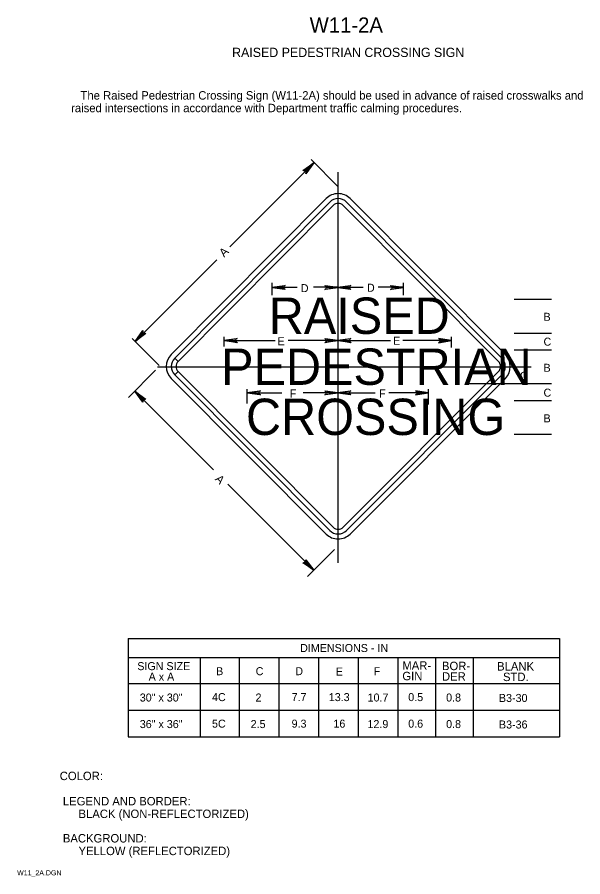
# Model space of a CAD drawing. Extents: x 0.013 to 0.18, y 0.004 to 0.259.
import ezdxf

# ---------------------------------------------------------------- set-up
doc = ezdxf.new("R2010")
doc.units = 0
for name, color, linetype in [('1', 7, 'Continuous'), ('2', 7, 'Continuous'), ('3', 7, 'Continuous')]:
    doc.layers.add(name, color=color, linetype=linetype)

msp = doc.modelspace()

# ---------------------------------------------------------------- linework, layer by layer
at = {"layer": '3'}
for p, q in [((0.07565765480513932, 0.1907872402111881), (0.10068094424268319, 0.21581052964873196)), ((0.10784039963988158, 0.20865107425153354), (0.09979705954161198, 0.21669441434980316)), ((0.10775, 0.213), (0.10775, 0.097125)), ((0.10426909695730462, 0.20512639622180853), (0.058315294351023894, 0.1588474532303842)), ((0.10532391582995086, 0.20407898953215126), (0.059370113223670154, 0.15780004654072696)), ((0.1563694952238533, 0.15780297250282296), (0.11030730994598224, 0.20408192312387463)), ((0.15742308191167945, 0.1588516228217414), (0.11136089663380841, 0.20513057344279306)), ((0.060368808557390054, 0.15680836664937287), (0.10632261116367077, 0.20308730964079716)), ((0.1093097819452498, 0.20308906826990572), (0.15537196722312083, 0.15681011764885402)), ((0.07180950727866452, 0.18693909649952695), (0.04762678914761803, 0.16275637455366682)), ((0.08825, 0.1765), (0.08825, 0.180125)), ((0.08831289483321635, 0.1788202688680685), (0.09562780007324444, 0.1788202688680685)), ((0.10781289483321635, 0.1788202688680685), (0.10056770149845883, 0.1788202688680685)), ((0.10781289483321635, 0.1788202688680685), (0.1152776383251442, 0.1788202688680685)), ((0.12731289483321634, 0.1788202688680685), (0.11966866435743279, 0.1788202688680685)), ((0.12725, 0.1765), (0.12725, 0.180125)), ((0.16, 0.17525000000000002), (0.171125, 0.17525000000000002)), ((0.05478624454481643, 0.1555969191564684), (0.04674290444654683, 0.163640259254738)), ((0.074, 0.16125), (0.074, 0.164125)), ((0.14150000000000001, 0.161), (0.14150000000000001, 0.164125)), ((0.16, 0.16525), (0.171125, 0.16525)), ((0.07406289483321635, 0.16303984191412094), (0.0891382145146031, 0.16303984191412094)), ((0.10781289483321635, 0.16303984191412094), (0.0929803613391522, 0.16303984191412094)), ((0.10781289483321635, 0.16303984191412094), (0.1233882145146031, 0.16303984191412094)), ((0.14156289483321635, 0.16303984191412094), (0.12701081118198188, 0.16303984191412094)), ((0.16, 0.16025), (0.171125, 0.16025)), ((0.059370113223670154, 0.15780004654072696), (0.060368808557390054, 0.15680836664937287)), ((0.060368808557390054, 0.15680836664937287), (0.059370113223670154, 0.15780004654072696)), ((0.05365338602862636, 0.15418554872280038), (0.045610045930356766, 0.14614221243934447)), ((0.05425, 0.15525), (0.16, 0.15525)), ((0.06037055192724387, 0.1538386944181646), (0.05937302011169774, 0.15284583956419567)), ((0.05937302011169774, 0.15284583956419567), (0.06037055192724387, 0.1538386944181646)), ((0.10632448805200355, 0.107667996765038), (0.060370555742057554, 0.1538386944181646)), ((0.1553702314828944, 0.15383693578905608), (0.10930817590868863, 0.10766624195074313)), ((0.16, 0.15525), (0.165125, 0.15525)), ((0.05831942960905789, 0.15179719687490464), (0.10427336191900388, 0.10562649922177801)), ((0.05937302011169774, 0.15284583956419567), (0.10532695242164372, 0.10667514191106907)), ((0.11030454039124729, 0.10667221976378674), (0.15636659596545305, 0.1528429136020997)), ((0.11135689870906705, 0.10562233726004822), (0.1574189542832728, 0.15179303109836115)), ((0.07086336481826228, 0.12464758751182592), (0.047489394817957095, 0.14802155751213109)), ((0.080875, 0.144375), (0.080875, 0.148625)), ((0.134625, 0.14400000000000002), (0.134625, 0.148625)), ((0.146, 0.15025), (0.171125, 0.15025)), ((0.08093789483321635, 0.14749420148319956), (0.091135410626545, 0.14749420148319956)), ((0.10781289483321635, 0.14749420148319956), (0.09748303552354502, 0.14749420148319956)), ((0.10781289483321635, 0.14753984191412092), (0.1187776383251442, 0.14753984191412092)), ((0.13468789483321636, 0.14753984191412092), (0.12283933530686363, 0.14753984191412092)), ((0.16, 0.14525), (0.171125, 0.14525)), ((0.16, 0.13525), (0.171125, 0.13525)), ((0.0751435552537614, 0.1203673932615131), (0.10062275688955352, 0.09488819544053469)), ((0.10678673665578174, 0.10105217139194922), (0.09874339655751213, 0.09300883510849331)), ((0.0455, 0.074625), (0.17350000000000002, 0.074625)), ((0.0455, 0.074625), (0.0455, 0.0455)), ((0.17350000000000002, 0.074625), (0.17350000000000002, 0.0455)), ((0.17350000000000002, 0.068875), (0.0455, 0.068875)), ((0.06687625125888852, 0.06888903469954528), (0.06687625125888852, 0.0455)), ((0.0785, 0.068875), (0.0785, 0.0455)), ((0.09025, 0.068875), (0.09025, 0.0455)), ((0.10200000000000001, 0.068875), (0.10200000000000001, 0.0455)), ((0.11375, 0.068875), (0.11375, 0.0455)), ((0.1255, 0.068875), (0.1255, 0.0455)), ((0.1367512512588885, 0.06888903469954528), (0.1367512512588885, 0.0455)), ((0.1478762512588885, 0.06888903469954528), (0.1478762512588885, 0.0455)), ((0.0455, 0.06125), (0.17350000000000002, 0.06125)), ((0.0455, 0.053375), (0.17350000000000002, 0.053375)), ((0.0455, 0.0455), (0.17350000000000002, 0.0455))]:
    msp.add_line(p, q, dxfattribs=at)
for points in [[(0.097625, 0.2135), (0.098, 0.213375), (0.100625, 0.21575), (0.097625, 0.2135), (0.097375, 0.2135), (0.100625, 0.21575), (0.09825, 0.213125), (0.098375, 0.212875), (0.100625, 0.21575), (0.09825, 0.2125), (0.098375, 0.212875)], [(0.092, 0.17825), (0.09175, 0.1785), (0.08825, 0.17875), (0.092, 0.17825), (0.092125, 0.178125), (0.08825, 0.17875), (0.09175, 0.178875), (0.091875, 0.17925), (0.08825, 0.17875), (0.092125, 0.179375), (0.091875, 0.17925)], [(0.10400000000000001, 0.17925), (0.10425, 0.179), (0.10775, 0.17875), (0.10400000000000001, 0.17925), (0.10387500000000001, 0.179375), (0.10775, 0.17875), (0.10425, 0.178625), (0.104125, 0.17825), (0.10775, 0.17875), (0.10387500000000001, 0.178125), (0.104125, 0.17825)], [(0.1115, 0.17825), (0.11125, 0.1785), (0.10775, 0.17875), (0.1115, 0.17825), (0.111625, 0.178125), (0.10775, 0.17875), (0.11125, 0.178875), (0.111375, 0.17925), (0.10775, 0.17875), (0.111625, 0.179375), (0.111375, 0.17925)], [(0.1235, 0.17925), (0.12375, 0.179), (0.12725, 0.17875), (0.1235, 0.17925), (0.123375, 0.179375), (0.12725, 0.17875), (0.12375, 0.178625), (0.123625, 0.17825), (0.12725, 0.17875), (0.123375, 0.178125), (0.123625, 0.17825)], [(0.0505, 0.165125), (0.05025, 0.165125), (0.047625, 0.16275), (0.0505, 0.165125), (0.05075, 0.165125), (0.047625, 0.16275), (0.05, 0.1655), (0.049875, 0.16575), (0.047625, 0.16275), (0.049875, 0.166), (0.049875, 0.16575)], [(0.07775, 0.1625), (0.0775, 0.16275), (0.074, 0.163), (0.07775, 0.1625), (0.077875, 0.162375), (0.074, 0.163), (0.0775, 0.163125), (0.077625, 0.1635), (0.074, 0.163), (0.077875, 0.163625), (0.077625, 0.1635)], [(0.10400000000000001, 0.1635), (0.10425, 0.16325), (0.10775, 0.163), (0.10400000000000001, 0.1635), (0.10387500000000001, 0.163625), (0.10775, 0.163), (0.10425, 0.162875), (0.104125, 0.1625), (0.10775, 0.163), (0.10387500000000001, 0.162375), (0.104125, 0.1625)], [(0.1115, 0.1625), (0.11125, 0.16275), (0.10775, 0.163), (0.1115, 0.1625), (0.111625, 0.162375), (0.10775, 0.163), (0.11125, 0.163125), (0.111375, 0.1635), (0.10775, 0.163), (0.111625, 0.163625), (0.111375, 0.1635)], [(0.13775, 0.1625), (0.138, 0.16275), (0.14150000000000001, 0.163), (0.13775, 0.1625), (0.137625, 0.162375), (0.14150000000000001, 0.163), (0.138, 0.163125), (0.137875, 0.1635), (0.14150000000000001, 0.163), (0.137625, 0.163625), (0.137875, 0.1635)], [(0.049875, 0.145), (0.049875, 0.14525), (0.0475, 0.148), (0.049875, 0.145), (0.049875, 0.14475), (0.0475, 0.148), (0.050125, 0.145625), (0.0505, 0.145625), (0.0475, 0.148), (0.05075, 0.145625), (0.0505, 0.145625)], [(0.084625, 0.147), (0.084375, 0.14725), (0.080875, 0.1475), (0.084625, 0.147), (0.08475, 0.146875), (0.080875, 0.1475), (0.084375, 0.147625), (0.0845, 0.148), (0.080875, 0.1475), (0.08475, 0.148125), (0.0845, 0.148)], [(0.10400000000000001, 0.148), (0.10425, 0.14775), (0.10775, 0.1475), (0.10400000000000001, 0.148), (0.10387500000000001, 0.148125), (0.10775, 0.1475), (0.10425, 0.147375), (0.104125, 0.147), (0.10775, 0.1475), (0.10387500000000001, 0.146875), (0.104125, 0.147)], [(0.1115, 0.147), (0.11125, 0.14725), (0.10775, 0.1475), (0.1115, 0.147), (0.111625, 0.146875), (0.10775, 0.1475), (0.11125, 0.147625), (0.111375, 0.148), (0.10775, 0.1475), (0.111625, 0.148125), (0.111375, 0.148)], [(0.130875, 0.147), (0.131125, 0.14725), (0.134625, 0.1475), (0.130875, 0.147), (0.13075, 0.146875), (0.134625, 0.1475), (0.131125, 0.147625), (0.131, 0.148), (0.134625, 0.1475), (0.13075, 0.148125), (0.131, 0.148)], [(0.09825, 0.09775), (0.09825, 0.0975), (0.100625, 0.094875), (0.09825, 0.09775), (0.09825, 0.098), (0.100625, 0.094875), (0.097875, 0.09725), (0.097625, 0.097125), (0.100625, 0.094875), (0.097375, 0.097125), (0.097625, 0.097125)]]:
    msp.add_lwpolyline(points, dxfattribs=at)
for centre, radius, start, end in [((0.10781707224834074, 0.20160334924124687), 0.005, 44.865505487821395, 135.2019845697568), ((0.10781707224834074, 0.20160334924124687), 0.0035134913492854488, 44.865505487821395, 135.2019845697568), ((0.10781707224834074, 0.20160334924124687), 0.002106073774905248, 44.86550301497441, 135.20198209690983), ((0.06186327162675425, 0.15532440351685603), 0.005, 135.2019810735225, 224.86518462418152), ((0.15387925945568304, 0.1553243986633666), 0.005, 315.067487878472, 44.86550335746), ((0.06186327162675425, 0.15532440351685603), 0.0035134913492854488, 135.2019810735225, 224.86518462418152), ((0.06186327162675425, 0.15532440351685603), 0.002106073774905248, 135.20198003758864, 224.86518358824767), ((0.15387925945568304, 0.1553243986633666), 0.002106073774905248, 315.06748671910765, 44.86550219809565), ((0.15387925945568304, 0.1553243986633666), 0.0035134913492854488, 315.067487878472, 44.86550335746), ((0.10781720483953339, 0.10915370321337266), 0.002106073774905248, 224.86518244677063, 315.0674867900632), ((0.10781720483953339, 0.10915370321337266), 0.005, 224.86518421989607, 315.0674885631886), ((0.10781720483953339, 0.10915370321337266), 0.0035134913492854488, 224.86518421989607, 315.0674885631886)]:
    msp.add_arc(centre, radius, start, end, dxfattribs=at)

# ---------------------------------------------------------------- texts
at = {"layer": '1'}
for s, height, p in [('W11-2A', 0.0045000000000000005, (0.099375, 0.254375)), ('RAISED PEDESTRIAN CROSSING SIGN', 0.00275025, (0.076375, 0.247125)), ('COLOR:', 0.0024997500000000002, (0.02525, 0.032625)), (' LEGEND AND BORDER:', 0.0024997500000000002, (0.02525, 0.025125)), ('      BLACK (NON-REFLECTORIZED)', 0.0024997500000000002, (0.02525, 0.021375)), (' BACKGROUND:', 0.0024997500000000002, (0.02525, 0.014125)), ('      YELLOW (REFLECTORIZED)', 0.0024997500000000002, (0.02525, 0.010375)), ('W11_2A.DGN', 0.0015, (0.012625, 0.004375))]:
    msp.add_text(s, height=height, dxfattribs=at).set_placement(p)
at = {"layer": '2'}
for s, p in [('   The Raised Pedestrian Crossing Sign (W11-2A) should be used in advance of raised crosswalks and ', (0.028625, 0.23450000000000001)), ('raised intersections in accordance with Department traffic calming procedures.', (0.028625, 0.23075025))]:
    msp.add_text(s, height=0.0024997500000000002, dxfattribs=at).set_placement(p)
at = {"layer": '3'}
for rotation, p in [(45, (0.074, 0.18762500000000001)), (315, (0.07112500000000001, 0.12175))]:
    msp.add_text('A', height=0.0024997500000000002, rotation=rotation, dxfattribs=at).set_placement(p)
for s, height, p in [('D', 0.0023752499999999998, (0.09675, 0.177375)), ('D', 0.0023752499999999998, (0.116375, 0.1775)), ('RAISED', 0.010779, (0.08725000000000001, 0.165)), ('B', 0.0023752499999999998, (0.16875, 0.168875)), ('E', 0.0023752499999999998, (0.089875, 0.161625)), ('E', 0.0023752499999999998, (0.124125, 0.16175)), ('C', 0.0023752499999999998, (0.16875, 0.1615)), ('PEDESTRIAN', 0.010779, (0.073125, 0.149875)), ('B', 0.0023752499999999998, (0.16875, 0.15375)), ('C', 0.0023752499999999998, (0.16175, 0.151375)), ('F', 0.0023752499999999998, (0.0935, 0.146125)), ('F', 0.0023752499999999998, (0.12, 0.146125)), ('C', 0.0023752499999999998, (0.16875, 0.146375)), ('CROSSING', 0.010779, (0.0805, 0.135)), ('B', 0.0023752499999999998, (0.16875, 0.13875)), ('DIMENSIONS - IN', 0.0023752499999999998, (0.09654229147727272, 0.07062500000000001)), ('SIGN SIZE', 0.0023752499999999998, (0.04825, 0.06525)), ('MAR-', 0.0024997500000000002, (0.12687500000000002, 0.065375)), ('BOR-', 0.0024997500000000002, (0.138625, 0.06525)), ('BLANK', 0.0024997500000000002, (0.15497461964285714, 0.065125)), ('A x A', 0.0023752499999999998, (0.051625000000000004, 0.062125)), ('B', 0.0023752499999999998, (0.07162500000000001, 0.06375)), ('C', 0.0023752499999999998, (0.083375, 0.06375)), ('D', 0.0023752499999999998, (0.095125, 0.06375)), ('E', 0.0023752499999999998, (0.107125, 0.063625)), ('F', 0.0023752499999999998, (0.11837500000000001, 0.06375)), ('GIN', 0.0024997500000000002, (0.12687500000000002, 0.06225)), ('DER', 0.0024997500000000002, (0.138625, 0.062125)), ('STD.', 0.0024997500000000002, (0.15672461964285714, 0.062)), ('30" x 30"', 0.0023752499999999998, (0.04899541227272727, 0.055937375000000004)), ('4C', 0.0023752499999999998, (0.07041457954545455, 0.056062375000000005)), ('2', 0.0023752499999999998, (0.08332353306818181, 0.055937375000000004)), ('7.7', 0.0023752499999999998, (0.09402914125, 0.056062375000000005)), ('13.3', 0.0023752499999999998, (0.10505828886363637, 0.056062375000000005)), ('10.7', 0.0023752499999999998, (0.11655936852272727, 0.055937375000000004)), ('0.5', 0.0023752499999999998, (0.1286213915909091, 0.056062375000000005)), ('0.8', 0.0023752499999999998, (0.1398555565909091, 0.055937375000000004)), ('B3-30', 0.0023752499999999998, (0.15551973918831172, 0.055812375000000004)), ('36" x 36"', 0.0023752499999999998, (0.04899541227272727, 0.048062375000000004)), ('5C', 0.0023752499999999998, (0.07041457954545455, 0.048187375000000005)), ('2.5', 0.0023752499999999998, (0.0818713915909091, 0.048062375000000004)), ('9.3', 0.0023752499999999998, (0.0940280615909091, 0.048187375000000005)), ('16', 0.0023752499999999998, (0.10642729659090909, 0.048187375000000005)), ('12.9', 0.0023752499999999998, (0.11652733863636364, 0.048062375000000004)), ('0.6', 0.0023752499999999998, (0.1286185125, 0.048187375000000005)), ('0.8', 0.0023752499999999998, (0.1398555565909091, 0.048062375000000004)), ('B3-36', 0.0023752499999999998, (0.15552477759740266, 0.047937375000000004))]:
    msp.add_text(s, height=height, dxfattribs=at).set_placement(p)

doc.saveas('drawing.dxf')
